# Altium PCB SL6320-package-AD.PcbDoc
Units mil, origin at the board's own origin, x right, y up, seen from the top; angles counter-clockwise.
Board outline 6000 x 4000 mil, 2 copper layers (Top Layer, Bottom Layer); 1 components, 0 nets, 33 pads, 0 vias.
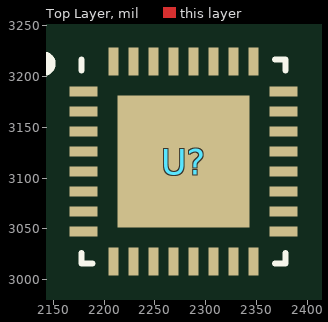
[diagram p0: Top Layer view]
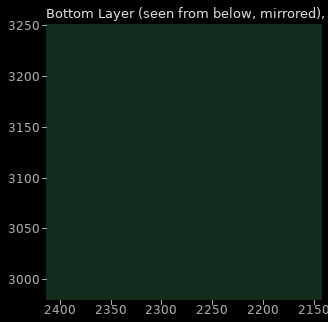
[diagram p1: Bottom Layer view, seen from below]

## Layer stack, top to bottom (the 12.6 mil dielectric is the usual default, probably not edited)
Top Layer: signal copper 1.4
Dielectric: dielectric 12.6, FR-4, Dk 4.8
Bottom Layer: signal copper 1.4

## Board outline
1000,1000 7000,1000 7000,5000 1000,5000

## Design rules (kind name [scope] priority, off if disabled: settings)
Clearance [All] p1: gap=10
PolygonConnect [All] p1: connectstyle=Relief reliefconductorwidth=10 reliefentries=4 polygonreliefangle="90 Angle"
RoutingVias [All] p1: holewidth=28 width=50 viastyle="Through Hole" minholewidth=28 minwidth=50 maxholewidth=28 maxwidth=50
SilkscreenOverComponentPads SilkToSolderMaskClearance [IsPad] p1: minsilkscreentomaskgap=10
SolderMaskExpansion [All] p1: expansion=4
Width [All] p1: maxlimit=10 minlimit=10 preferedwidth=10
27 further rules are at their usual default settings.

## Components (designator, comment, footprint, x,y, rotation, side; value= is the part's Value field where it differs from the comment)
U? "SL6320" Z_QFN50P500X500X100-32N 2180,3185 r270 top (schematic designator U4)

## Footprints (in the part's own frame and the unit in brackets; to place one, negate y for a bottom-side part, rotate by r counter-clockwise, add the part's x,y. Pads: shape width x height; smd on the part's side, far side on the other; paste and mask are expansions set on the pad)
Z_QFN50P500X500X100-32N [mm] "QFN32"
  rect 0.25x0.7 smd: 1(0,0) 2(0.5,0) 3(1,0) 4(1.5,0) 5(2,0) 6(2.5,0) 7(3,0) 8(3.5,0) 17(3.5,5) 18(3,5) 19(2.5,5) 20(2,5) 21(1.5,5) 22(1,5) 23(0.5,5) 24(0,5)
  rect 0.7x0.25 smd: 9(4.25,0.75) 10(4.25,1.25) 11(4.25,1.75) 12(4.25,2.25) 13(4.25,2.75) 14(4.25,3.25) 15(4.25,3.75) 16(4.25,4.25) 25(-0.75,4.25) 26(-0.75,3.75) 27(-0.75,3.25) 28(-0.75,2.75) 29(-0.75,2.25) 30(-0.75,1.75) 31(-0.75,1.25) 32(-0.75,0.75)
  rect 3.3x3.3 smd paste-5 mask+0.102: 33(1.75,2.5)
  silkscreen extent -0.85,-1.15 4.3,5.05, body extent -0.8,-0.05 4.3,5.05, height 1

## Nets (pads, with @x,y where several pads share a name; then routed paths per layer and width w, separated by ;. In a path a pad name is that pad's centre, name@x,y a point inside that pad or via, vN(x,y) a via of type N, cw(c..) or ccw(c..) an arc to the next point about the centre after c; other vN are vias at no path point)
pads on no net: U?.1 U?.2 U?.3 U?.4 U?.5 U?.6 U?.7 U?.8 U?.9 U?.10 U?.11 U?.12 U?.13 U?.14 U?.15 U?.16 U?.17 U?.18 U?.19 U?.20 U?.21 U?.22 U?.23 U?.24 U?.25 U?.26 U?.27 U?.28 U?.29 U?.30 U?.31 U?.32 U?.33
